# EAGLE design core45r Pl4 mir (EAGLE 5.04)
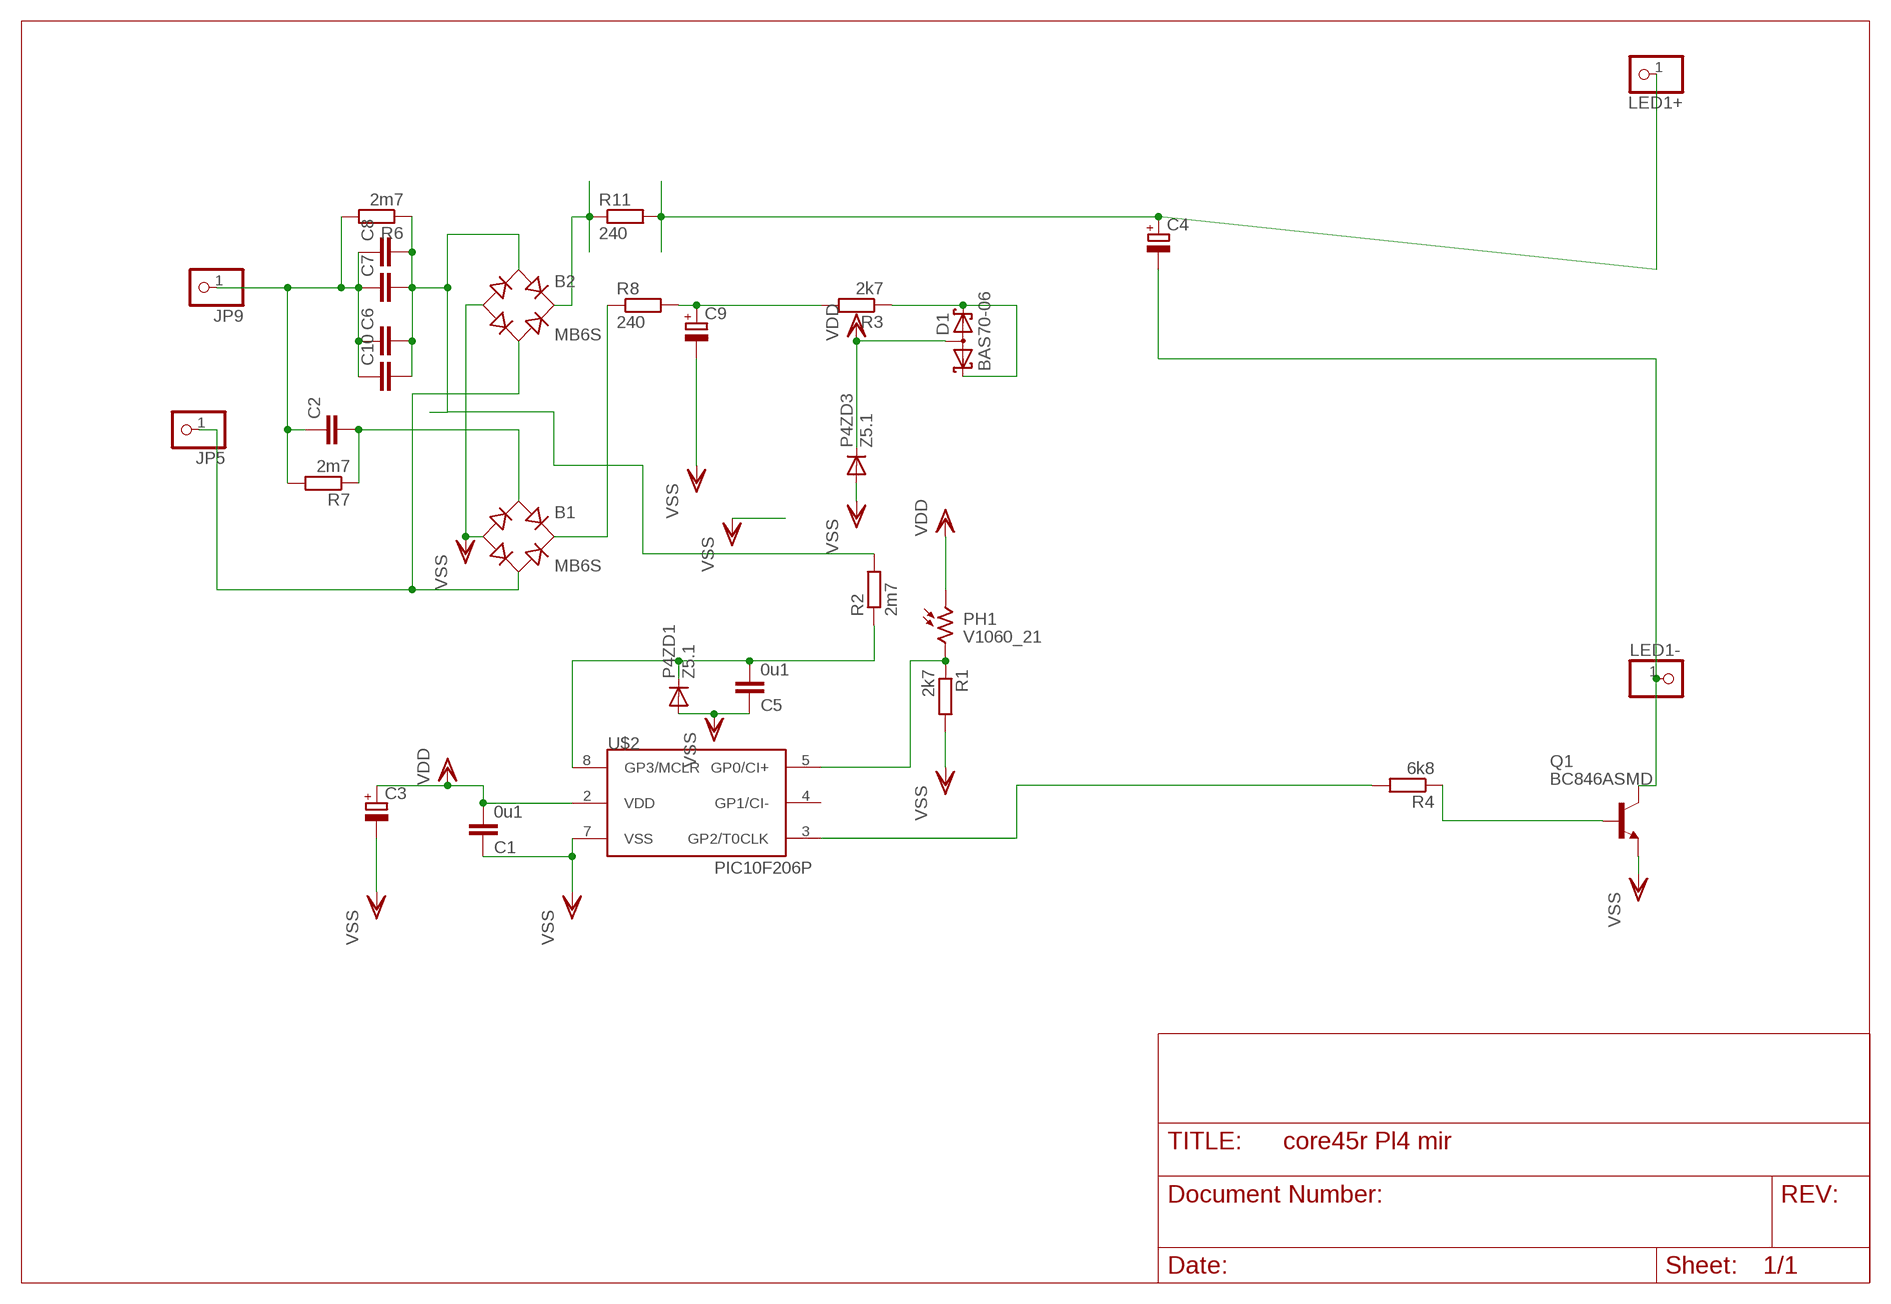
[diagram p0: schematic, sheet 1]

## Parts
B1  MB6S  [SOIC-4]
B2  MB6S  [SOIC-4]
C1  0u1  C-EUC1206  [C1206]
C2  C-EU075-052X106  [C075-052X106]
C3  CPOL-EU5-13  [2,5-5-FLAT]
C4  CPOL-EUTT5D11L  [TT5D11L]
C5  0u1  C-EUC1206  [C1206]
C6  C-EU150-064X183  [C150-064X183]
C7  C-EU150-054X183  [C150-054X183]
C8  C-EU150-054X183  [C150-054X183]
C9  CPOL-EUTT5D11L  [TT5D11L]
C10  C-EU150-064X183  [C150-064X183]
D1  BAS70-06  [SOT23]
JP5  PINHD-1X1  [1X01]
JP9  PINHD-1X1  [1X01]
LED1+  PINHD-1X1  [1X01]
LED1-  PINHD-1X1  [1X01]
P4ZD1  Z5.1  DIODE-MINIMELF  [MINIMELF]
P4ZD3  Z5.1  DIODE-MINIMELF  [MINIMELF]
PH1  V1060_21  [TO-5_V10]
Q1  BC846ASMD  [SOT23]
R1  2k7  R-EU_R0805  [R0805]
R2  2m7  R-EU_R1206  [R1206]
R3  2k7  R-EU_R0805  [R0805]
R4  6k8  R-EU_R1206  [R1206]
R6  2m7  R-EU_0207/10  [0207/10]
R7  2m7  R-EU_0204/7  [0204/7]
R8  240  R-EU_0204/5  [0204/5]
R11  240  R-EU_0204/7  [0204/7]
U$2  PIC10F206P  [DIL8]

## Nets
AC1: B1.~2(AC2) B2.~2(AC2) JP5.1
AC2: C2.1 C6.1 C7.1 C8.1 C10.1 JP9.1 R6.2 R7.2
CBIG: B2.~1(AC1) C6.2 C7.2 C8.2 C10.2 R2.2 R6.1
D+: C4.+ LED1+.1 R11.2
D-: C4.- LED1-.1 Q1.3(C)
DR+: C9.+ R3.2 R8.2
N$1: C5.2 P4ZD1.C R2.1 U$2.8(GP3/MCLR)
N$5: D1.1(K1) D1.2(K2) R3.1
N$8: B1.~1(AC1) C2.2 R7.1
N$11: B2.+ R11.1
N$12: Q1.1(B) R4.1
N$15: R4.2 U$2.3(GP2/T0CLK)
N$17: PH1.2 R1.1 U$2.5(GP0/CI+)
RECDR+: B1.+ R8.1
VDD: C1.2 C3.+ D1.3(AA) P4ZD3.C PH1.1 U$2.2(VDD)
VSS: B1.- B2.- C1.1 C3.- C5.1 C9.- P4ZD1.A P4ZD3.A Q1.2(E) R1.2 U$2.7(VSS)
Unconnected: U$2.4(GP1/CI-)

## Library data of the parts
B1 B2 = rectifier:MB*S: Bridge Rectifier Source: http://www.fairchildsemi.com/ds/MB/MB6S.pdf
C1 C5 = rcl:C-EU: CAPACITOR, European symbol
C2 C6-C8 C10 = rcl-2:C-EU: CAPACITOR, European symbol
C3 C4 C9 = rcl-2:CPOL-EU: POLARIZED CAPACITOR, European symbol
D1 = diode:BAS70-06: Silicon Schottky Diodes General-purpose diode for high-speed switching
JP5 JP9 LED1+ LED1- = pinhead(2):PINHD-1X1: PIN HEADER
P4ZD1 P4ZD3 = diode:DIODE-: DIODE
PH1 = photo-elements:?1060*: Sensor Street Light control
Q1 = transistor-npn:BC846*: NPN Transistor
R1-R4 R6-R8 R11 = rcl-2:R-EU_: RESISTOR, European symbol
U$2 = microchip-3:PIC10F2*: uPC nW 0,25/0,5k Program Flash memory Comparator

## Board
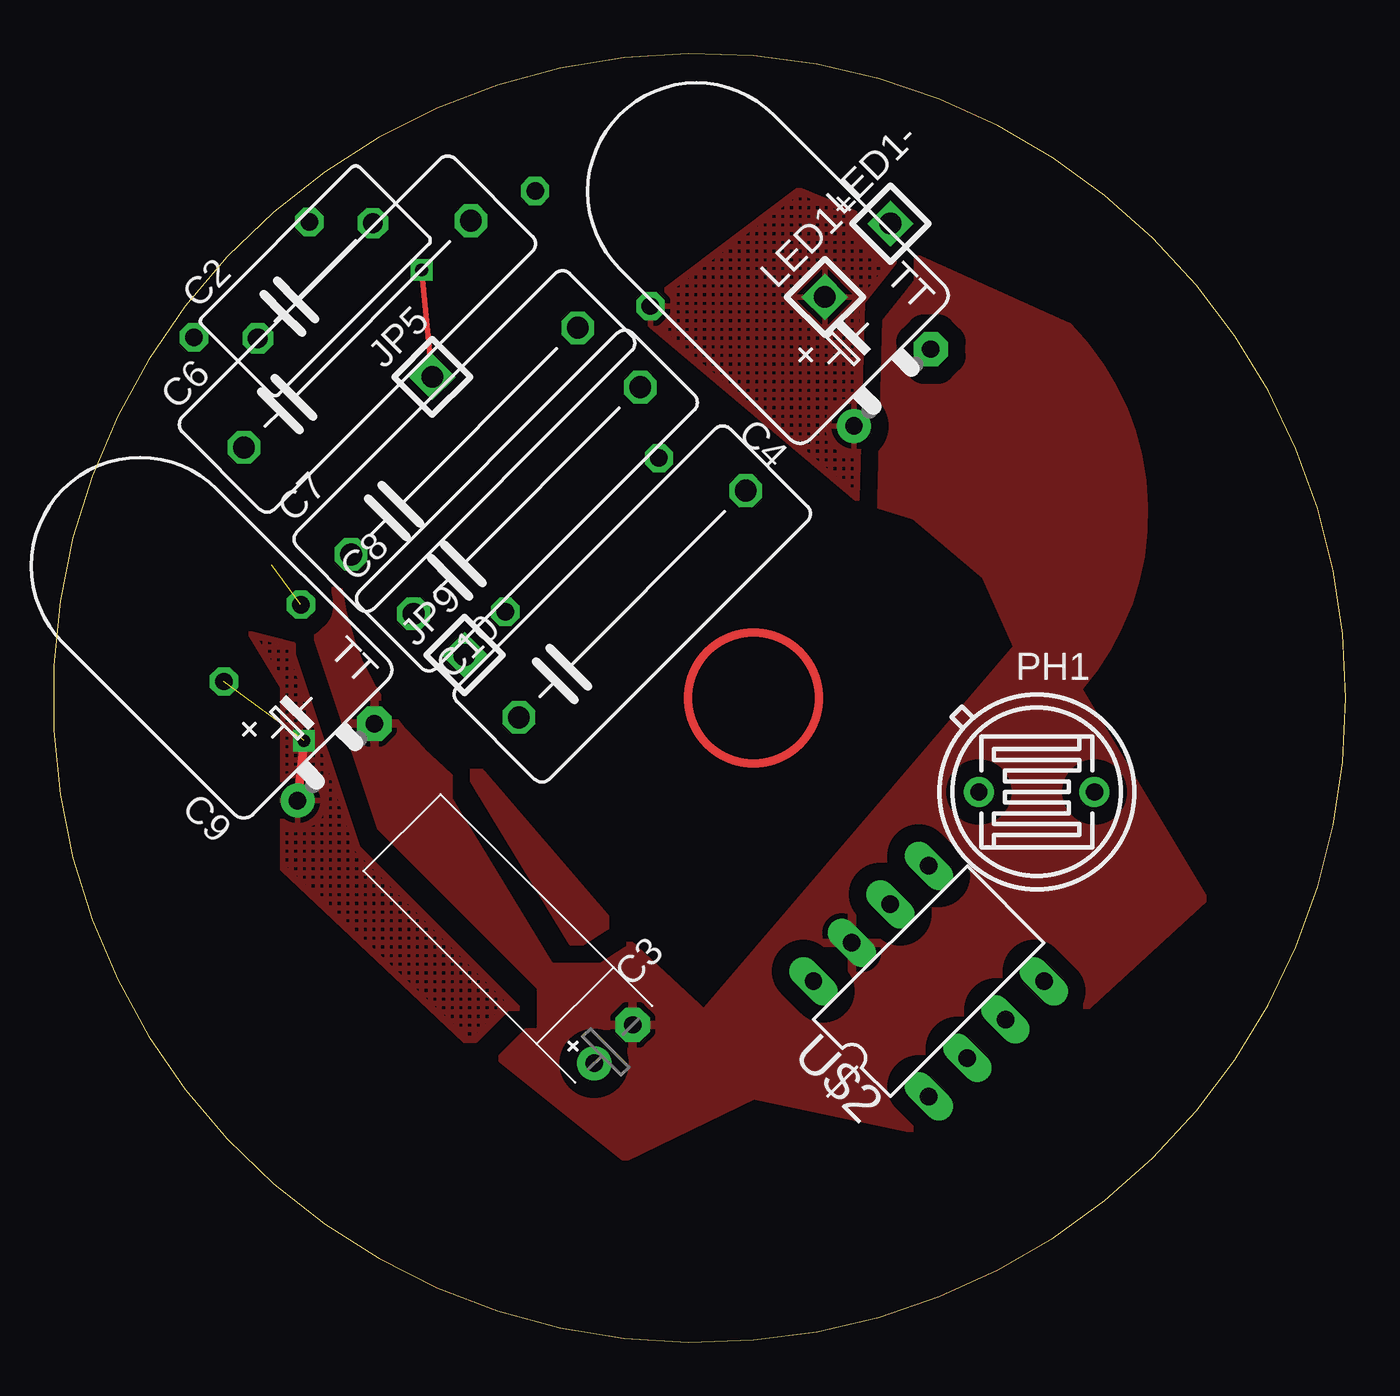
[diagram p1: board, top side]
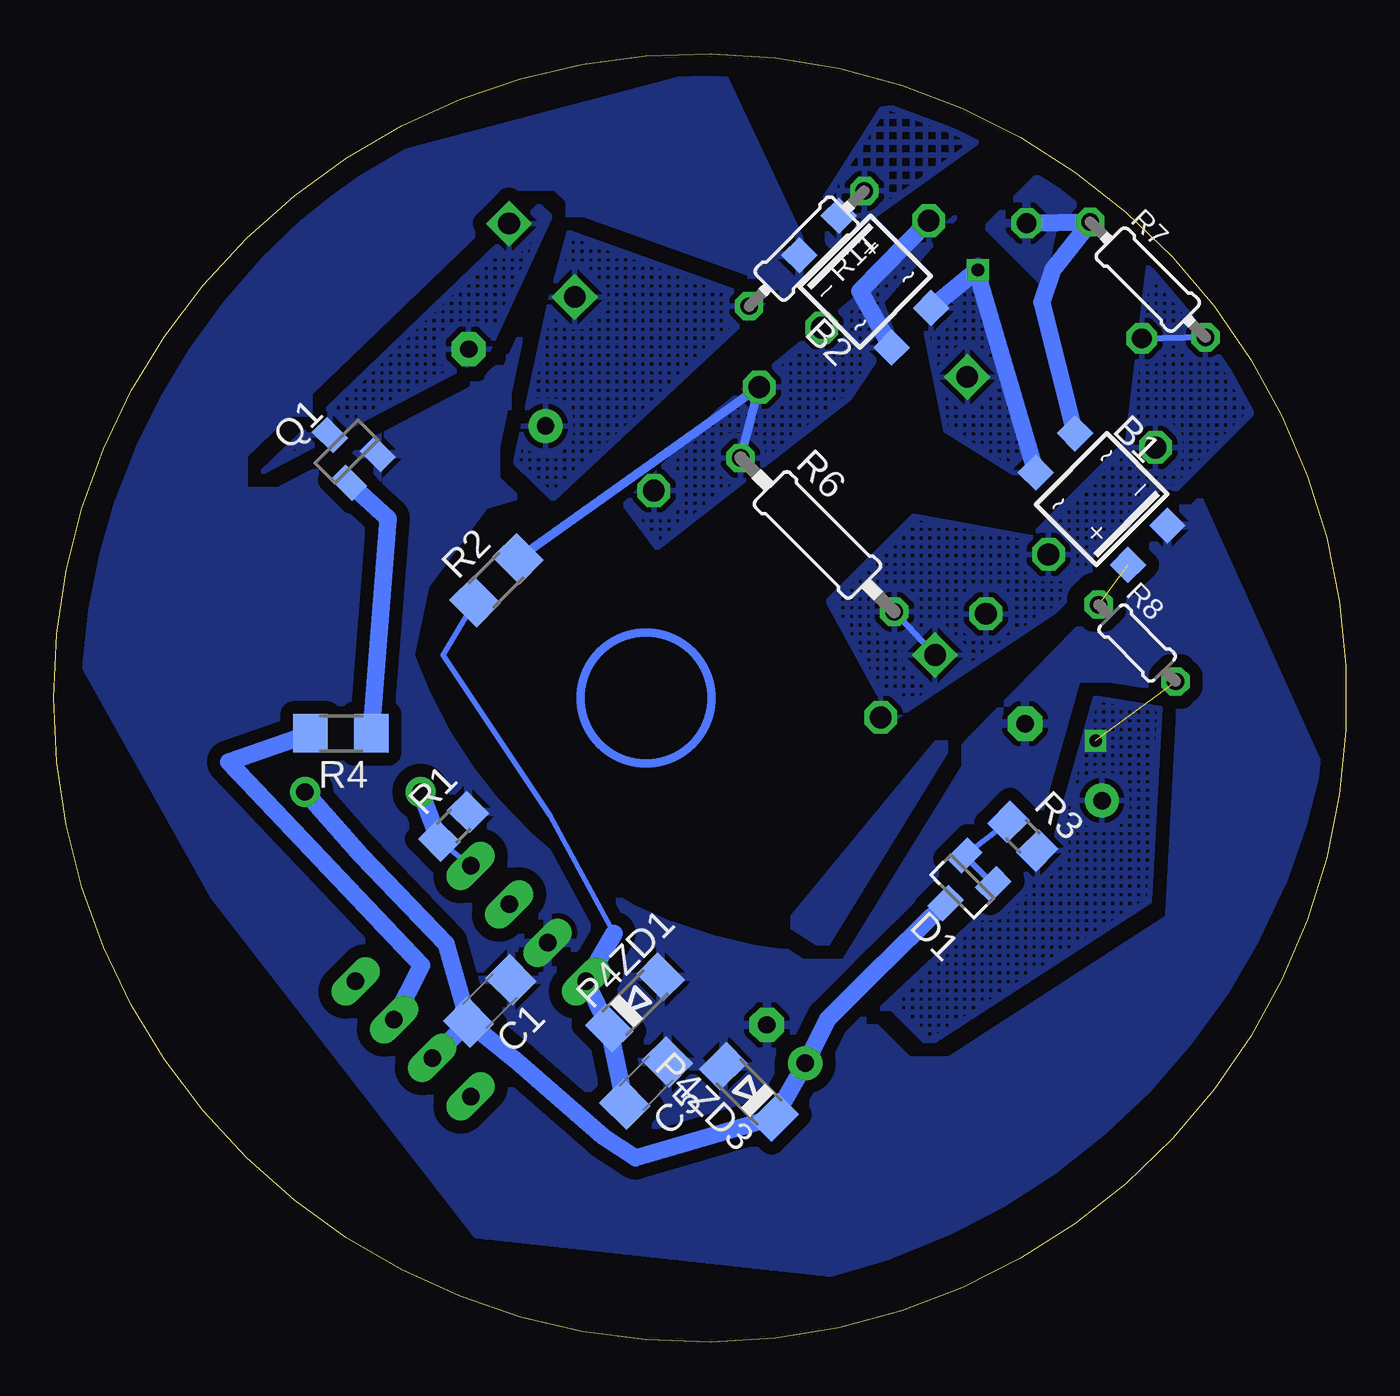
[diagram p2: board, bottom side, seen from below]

Size 60.4 x 60.22 mm. Coordinates in mm from the lower left corner, seen from the top.
Outline: 32.7,0.11 arc171 32.7,60.11 arc190 32.7,0.11
Copper layers (1*16): Top 0.035mm / dielectric 1.5mm / Bottom 0.035mm
Design rules "default": minimum track width 10mil, minimum drill 24mil, track to track 8mil, track to pad 8mil, pad to pad 8mil, via to via 8mil, smd to smd 8mil, copper to edge 40mil, drill to drill 8mil, minimum pad ring 10mil, minimum via ring 8mil, stop-mask expansion 4mil, vias tented up to drill 0mil, thermal gap 10mil

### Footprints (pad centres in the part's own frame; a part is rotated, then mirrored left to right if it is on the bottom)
SOIC-4 = smd 1.2 x 1.2: + 1.3,3.05; - -1.3,3.05; ~1 -1.3,-3.05; ~2 1.3,-3.05
C1206 = smd 1.6 x 1.8: 1 -1.4,0; 2 1.4,0
C075-052X106 = drill 0.914 octagon: 1 -3.81,0; 2 3.81,0
2,5-5-FLAT = drill 0.813 pad 1.6 round: + -1.27,0 | drill 0.813 pad 1.6 octagon: - 1.27,0
TT5D11L = drill 0.813 pad 1.6 round: + -2.54,0 | drill 0.813 pad 1.6 octagon: - 2.54,0
C150-064X183 = drill 1.016 octagon: 1 -7.493,0; 2 7.493,0
C150-054X183 = drill 1.016 octagon: 1 -7.493,0; 2 7.493,0
SOT23 = smd 1 x 1.4: 1 -0.95,-1.1; 2 0.95,-1.1; 3 0,1.1
1X01 = drill 1.016 square: 1 0,0
MINIMELF = smd 1.4 x 1.8: A 1.7,0; C -1.7,0
TO-5_V10 = drill 0.8 pad 1.4 round: 1 -2.7,0; 2 2.7,0
R0805 = smd 1.3 x 1.5: 1 -0.95,0; 2 0.95,0
R1206 = smd 1.6 x 1.803: 1 -1.422,0; 2 1.422,0
0207/10 = drill 0.813 octagon: 1 -5.08,0; 2 5.08,0
0204/7 = drill 0.813 octagon: 1 -3.81,0; 2 3.81,0
0204/5 = drill 0.813 octagon: 1 -2.54,0; 2 2.54,0
DIL8 = drill 0.813 long: 1 -3.81,-3.81; 2 -1.27,-3.81; 3 1.27,-3.81; 4 3.81,-3.81; 5 3.81,3.81; 6 1.27,3.81; 7 -1.27,3.81; 8 -3.81,3.81

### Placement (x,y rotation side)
B1  11.43,39.4 225 bottom
B2  22.47,49.57 45 bottom
C1  40.01,15.95 225 bottom
C2  12.24,49.6 45 top
C3  26.17,13.93 45 top
C4  39.2,44.61 45 top
C5  32.7,12.11 225 bottom
C6  14.2,47.11 45 top
C7  19.2,42.11 45 top
C8  22.12,39.34 45 top
C9  13.2,27.11 45 top
C10  27.05,34.5 45 top
D1  17.93,21.3 135 bottom
JP5  17.7,45.11 45 top
JP9  19.2,32.11 45 top
LED1+  36.04,48.85 45 top
LED1-  39.11,52.28 45 top
P4ZD1  33.23,15.87 45 bottom
P4ZD3  27.9,11.7 135 bottom
PH1  45.95,25.72 180 top
Q1  46.7,41.61 45 bottom
R1  41.7,24.11 45 bottom
R2  39.7,35.61 45 bottom
R3  15.1,23.65 315 bottom
R4  46.97,28.45 180 bottom
R6  24.7,37.73 315 bottom
R7  9.26,49.66 315 bottom
R8  9.76,32.68 315 bottom
R11  25.2,51.11 225 bottom
U$2  40.9,16.87 45 top

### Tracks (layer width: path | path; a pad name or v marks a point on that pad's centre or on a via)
AC1  (via drill 0.6)
  Top 0.254: v17.2,50.11 JP5.1
  Bottom 0.254: 17.27,50.07 v17.2,50.11
  Bottom 0.813: B1.~2 17.27,50.07 B2.~2
  pour Bottom (isolate 0.61, hatched): 17.2,50.61 19.7,47.61 18.7,42.61 14.7,40.11
AC2
  Bottom 0.305: JP9.1 R6.2 | R7.2 C2.1
  pour Bottom (isolate 0.813, rank 2, hatched): 3.2,44.61 9.2,50.61 10.2,42.11 14.7,37.61 20.2,38.61 24.2,34.61 21.2,29.11 13.7,34.11
CBIG
  Bottom 0.406: R6.1 C8.2 R2.2
  Bottom 0.813: B2.~1 22.7,49.11 C6.2
  pour Bottom (isolate 0.61, hatched): 29.2,43.61 33.7,39.11 32.2,37.11 23.2,44.11 21.2,47.11 21.7,48.61 18.2,52.61
D+
  pour Bottom (isolate 0.406, hatched): 36.3,51.86 37.2,48.61 38.8,41.11 37.05,39.41 27.2,48.61
  pour Top (isolate 0.61, hatched): 34.8,53.86 40.2,51.61 37.8,48.61 37.55,39.41 27.2,48.11
D-
  pour Bottom (isolate 0.406, rank 2, hatched): 37.7,53.11 50.7,40.61 40.2,46.11 37.2,52.61
DR+  (via drill 0.6)  (1 unrouted)
  Top 0.406: C9.+ v11.7,28.11
  pour Bottom (isolate 0.61, hatched): 8.7,29.61 11.7,30.11 13.7,23.11 21.7,15.61 21.2,15.61 19.7,14.11 19.2,14.11 9.2,20.61
  pour Top (isolate 0.813, hatched): 10.7,30.61 9.2,33.11 11.2,32.61 11.2,32.11 14.2,23.11 21.7,15.61 21.2,15.61 19.7,14.11 19.2,14.11 10.7,22.11
N$1
  Bottom 0.254: R2.1 42.2,32.11 37.2,24.61 34.2,19.11
  Bottom 0.813: 34.2,19.11 U$2.8 P4ZD1.C C5.2
N$5
  Bottom 0.254: R3.1 D1.2 D1.1
N$8
  Bottom 0.813: C2.2 R7.1 13.7,50.11 14.2,48.61 B1.~1
  pour Bottom (isolate 0.61): 13.7,52.11 12.7,53.11 14.2,54.61 16.7,52.11 14.2,49.61
N$11
  pour Bottom (isolate 0.61, hatched): 24.2,51.11 24.3,53.56 21.7,57.61 18.2,58.11 17.2,56.11
N$12
  Bottom 0.813: Q1.1 44.75,38.5 R4.1
N$15
  Bottom 0.813: U$2.3 43.2,17.61 52.2,27.11 R4.2
N$17
  Bottom 0.254: U$2.5 R1.1
  Bottom 0.813: R1.1 PH1.2
RECDR+  (1 unrouted)
  pour Bottom (isolate 0.61): 18.7,28.11 24.45,18.81 25.7,19.61
  pour Top (isolate 0.61): 19.7,26.61 24.45,18.81 25.7,19.61
VDD
  Bottom 0.813: C1.2 38.7,13.11 34.7,9.61 33.2,8.61 P4ZD3.C C3.+ 24.2,15.11 22.2,17.11 D1.3 | C1.2 42.05,18.61 46.05,22.76 PH1.1 | C1.2 U$2.2
VSS
  pour Bottom (isolate 0.61, rank 5): 1.3,27.03 7.04,39.77 10.7,35.11 26.57,18.86 25.7,18.11 arc66 43.7,32.11 43.04,35.33 40.24,39.13 34.99,40.63 32.43,43.19 24.93,50.31 29.23,59.46 44.43,55.46 arc-55 58.86,31.53 52.86,20.82 40.64,5.04 24.08,3.24 arc-64
  pour Top (isolate 0.813, rank 5): 3.95,26.83 arc-76 25.04,52.27 25.66,49.77 arc135 17.2,27.61 30.4,15.36 45.04,32.5 43.54,35.83 40.24,38.63 36.99,39.63 33.93,43.69 34.23,50.01 26.27,49.63 26.57,52.8 29.73,55.46 47.43,47.46 arc-85 47.86,30.53 53.76,20.72 41.69,9.64 32.73,11.54 26.7,8.61
(copper drawn outside any net)
  shapes: Bottom circle x1, Top circle x1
